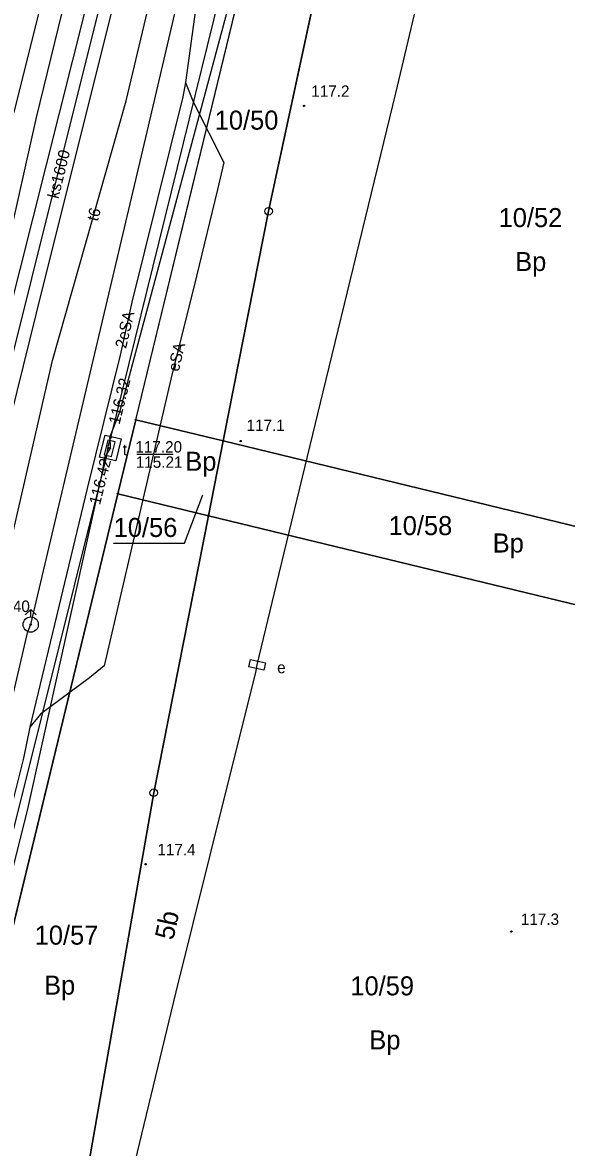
# Model space of a CAD drawing. Extents: x 6424617 to 6425697, y 5665845 to 5667190.
# Drawn here: x 6425314 to 6425349.8, y 5666069.8 to 5666143.7 of the extents above; entities that cross this region are included whole.
import ezdxf

# ---------------------------------------------------------------- set-up
doc = ezdxf.new("R2010")
doc.units = 0
for name, color, linetype in [('Warstwa 1', 7, 'Continuous'), ('Warstwa 10', 7, 'Continuous'), ('Warstwa 11', 7, 'Continuous'), ('Warstwa 12', 7, 'Continuous'), ('Warstwa 13', 7, 'Continuous'), ('Warstwa 14', 7, 'Continuous'), ('Warstwa 15', 7, 'Continuous'), ('Warstwa 16', 7, 'Continuous'), ('Warstwa 2', 7, 'Continuous'), ('Warstwa 21', 7, 'Continuous'), ('Warstwa 4', 7, 'Continuous'), ('Warstwa 5', 7, 'Continuous'), ('Warstwa 6', 7, 'Continuous'), ('Warstwa 61', 7, 'Continuous'), ('Warstwa 9', 7, 'Continuous')]:
    doc.layers.add(name, color=color, linetype=linetype)

msp = doc.modelspace()

# ---------------------------------------------------------------- linework, layer by layer
at = {"layer": 'Warstwa 1'}
for p, q in [((6425321.48, 5666117.61), (6425331.55, 5666159.11)), ((6425321.48, 5666117.61), (6425331.55, 5666159.11)), ((6425330.199, 5666131.309), (6425335.94, 5666158.04)), ((6425330.199, 5666131.309), (6425335.94, 5666158.04)), ((6425327.22, 5666116.22), (6425330.199, 5666131.309)), ((6425327.22, 5666116.22), (6425330.199, 5666131.309)), ((6425320.3, 5666112.75), (6425321.48, 5666117.61)), ((6425320.3, 5666112.75), (6425321.48, 5666117.61)), ((6425321.48, 5666117.61), (6425327.22, 5666116.22)), ((6425321.48, 5666117.61), (6425327.22, 5666116.22)), ((6425326.25, 5666111.31), (6425327.22, 5666116.22)), ((6425326.25, 5666111.31), (6425327.22, 5666116.22)), ((6425327.22, 5666116.22), (6425364.28, 5666107.23)), ((6425327.22, 5666116.22), (6425364.28, 5666107.23)), ((6425307.383, 5666059.502), (6425320.3, 5666112.75)), ((6425307.383, 5666059.502), (6425320.3, 5666112.75)), ((6425320.3, 5666112.75), (6425326.25, 5666111.31)), ((6425320.3, 5666112.75), (6425326.25, 5666111.31)), ((6425322.659, 5666093.11), (6425326.25, 5666111.31)), ((6425322.659, 5666093.11), (6425326.25, 5666111.31)), ((6425326.25, 5666111.31), (6425363.13, 5666102.36)), ((6425326.25, 5666111.31), (6425363.13, 5666102.36)), ((6425314.293, 5666045.457), (6425322.659, 5666093.11)), ((6425314.293, 5666045.457), (6425322.659, 5666093.11))]:
    msp.add_line(p, q, dxfattribs=at)
at = {"layer": 'Warstwa 10'}
for points in [[(6425366.705, 5666313.952), (6425364.98, 5666307.394), (6425362.943, 5666299.196), (6425357.643, 5666277.187), (6425356.335, 5666271.53), (6425352.738, 5666256.719), (6425351.907, 5666252.99), (6425349.316, 5666242.152), (6425345.12, 5666224.971), (6425343.235, 5666216.898), (6425341.343, 5666209.098), (6425332.507, 5666173.528), (6425329.622, 5666162.257), (6425325.627, 5666146.18), (6425324.735, 5666139.771)], [(6425324.735, 5666139.771), (6425325.272, 5666138.452), (6425327.252, 5666134.518), (6425326.853, 5666132.742), (6425325.46, 5666127.052), (6425323.784, 5666120.273), (6425319.4, 5666101.45), (6425318.435, 5666100.665), (6425315.212, 5666098.266), (6425314.516, 5666097.411)], [(6425324.735, 5666139.771), (6425324.567, 5666138.82), (6425321.214, 5666125.338), (6425320.452, 5666121.863), (6425318.28, 5666113.101), (6425314.516, 5666097.411)], [(6425314.516, 5666097.411), (6425314.113, 5666095.387), (6425310.83, 5666082.329), (6425309.435, 5666076.765), (6425308.31, 5666071.803), (6425306.533, 5666064.673)]]:
    msp.add_lwpolyline(points, dxfattribs=at)
for centre in [(6425330.199, 5666131.309), (6425322.659, 5666093.11)]:
    msp.add_circle(centre, 0.25, dxfattribs=at)
at = {"layer": 'Warstwa 12'}
for points in [[(6425305.154, 5666064.69), (6425312.938, 5666097.478), (6425314.389, 5666103.694), (6425314.577, 5666104.157), (6425322.215, 5666136.517), (6425325.077, 5666148.728), (6425327.095, 5666157.317), (6425332.422, 5666179.712), (6425334.472, 5666188.347), (6425337.66, 5666202.127), (6425337.727, 5666202.623), (6425340.397, 5666213.727), (6425347.877, 5666245.554), (6425350.108, 5666255.243), (6425354.52, 5666274.46), (6425358.124, 5666289.983), (6425360.543, 5666300.182), (6425364.084, 5666313.984)], [(6425302.996, 5666064.716), (6425303.371, 5666066.959), (6425303.474, 5666067.683), (6425303.814, 5666068.412), (6425304.651, 5666073.489), (6425307.939, 5666085.989), (6425311.229, 5666100.781), (6425315.998, 5666121.507), (6425320.84, 5666138.568), (6425327.293, 5666165.729), (6425330.741, 5666179.714), (6425331.41, 5666183.678), (6425331.223, 5666184.439), (6425337.86, 5666212.626), (6425344.087, 5666240.981), (6425358.931, 5666300.334), (6425358.838, 5666300.979)], [(6425320.382, 5666064.506), (6425324.122, 5666080.024), (6425327.46, 5666093.416), (6425329.355, 5666100.998), (6425329.449, 5666101.506), (6425330.718, 5666106.78), (6425333.785, 5666119.439), (6425338.549, 5666139.062), (6425341.864, 5666153.037), (6425342.705, 5666156.012), (6425344.677, 5666164.319), (6425345.935, 5666169.368), (6425348.182, 5666178.762), (6425351.749, 5666193.731), (6425354.241, 5666204.098)], [(6425338.063, 5666190.341), (6425337.711, 5666188.983), (6425319.81, 5666116.414), (6425319.643, 5666115.857), (6425319.556, 5666115.245), (6425306.92, 5666064.668)], [(6425307.484, 5666064.661), (6425308.087, 5666066.909), (6425314.371, 5666091.949), (6425319.287, 5666114.171), (6425319.45, 5666115.139), (6425319.807, 5666115.746), (6425319.784, 5666116.517), (6425320.436, 5666118.136), (6425328.2, 5666147.128), (6425329.097, 5666150.261), (6425330.794, 5666156.413), (6425337.552, 5666188.452), (6425337.922, 5666190.227)], [(6425327.353, 5666180.631), (6425325.599, 5666173.711), (6425322.908, 5666163.318), (6425318.178, 5666144.632), (6425313.866, 5666127.482), (6425308.085, 5666104.552), (6425305.278, 5666093.33), (6425304.482, 5666090.216)], [(6425306.182, 5666089.671), (6425311.135, 5666109.171), (6425315.382, 5666126.297), (6425321.264, 5666149.87), (6425326.891, 5666171.984), (6425329.037, 5666180.221)]]:
    msp.add_lwpolyline(points, dxfattribs=at)
for centre in [(6425321.48, 5666117.61), (6425327.22, 5666116.22), (6425320.3, 5666112.75), (6425326.25, 5666111.31)]:
    msp.add_circle(centre, 0.045, dxfattribs=at)
at = {"layer": 'Warstwa 13'}
for centre in [(6425332.534, 5666138.227), (6425328.357, 5666116.207), (6425322.123, 5666088.408), (6425346.141, 5666083.992)]:
    msp.add_circle(centre, 0.045, dxfattribs=at)
at = {"layer": 'Warstwa 14'}
msp.add_line((6425323.929, 5666115.33), (6425321.549, 5666115.33), dxfattribs=at)
for centre in [(6425319.81, 5666116.414), (6425319.768, 5666115.733), (6425319.45, 5666115.139), (6425314.577, 5666104.157)]:
    msp.add_circle(centre, 0.045, dxfattribs=at)
at = {"layer": 'Warstwa 15'}
msp.add_lwpolyline([(6425320.024, 5666109.5), (6425324.669, 5666109.5), (6425325.872, 5666112.681)], dxfattribs=at)
at = {"layer": 'Warstwa 16'}
msp.add_lwpolyline([(6425319.457, 5666116.589), (6425320.507, 5666116.348), (6425320.166, 5666114.902), (6425319.098, 5666115.153)], close=True, dxfattribs=at)
at = {"layer": 'Warstwa 21'}
msp.add_lwpolyline([(6425329.881, 5666101.151), (6425328.906, 5666101.373), (6425329.017, 5666101.861), (6425329.992, 5666101.639), (6425329.881, 5666101.151)], dxfattribs=at)
at = {"layer": 'Warstwa 4'}
msp.add_lwpolyline([(6425319.893, 5666115.188), (6425320.129, 5666116.16), (6425319.643, 5666116.278), (6425319.407, 5666115.306)], close=True, dxfattribs=at)
for points in [[(6425314.223, 5666104.803), (6425314.577, 5666105.157)], [(6425314.931, 5666104.803), (6425314.577, 5666105.157)], [(6425314.577, 5666104.657), (6425314.577, 5666105.157)]]:
    msp.add_lwpolyline(points, dxfattribs=at)
msp.add_circle((6425314.577, 5666104.157), 0.5, dxfattribs=at)
at = {"layer": 'Warstwa 5'}
msp.add_line((6425313.49, 5666137.803), (6425317.654, 5666154.563), dxfattribs=at)
at = {"layer": 'Warstwa 6'}
msp.add_lwpolyline([(6425325.89, 5666241.74), (6425306.64, 5666159.22), (6425302.03, 5666141.46), (6425286.06, 5666058.16), (6425282.55, 5666028.38), (6425277.55, 5665972.9), (6425261.42, 5665964.23), (6425258.752, 5665937.662), (6425276.622, 5665932.707), (6425278.506, 5665940.485), (6425294.186, 5666005.104), (6425300.721, 5666032.019), (6425302.837, 5666040.775), (6425307.383, 5666059.502), (6425320.3, 5666112.75), (6425321.48, 5666117.61), (6425331.55, 5666159.11), (6425352.539, 5666245.598)], dxfattribs=at)
for points in [[(6425335.94, 5666158.04), (6425330.199, 5666131.309), (6425327.22, 5666116.22), (6425321.48, 5666117.61), (6425331.55, 5666159.11)], [(6425335.94, 5666158.04), (6425330.199, 5666131.309), (6425327.22, 5666116.22), (6425364.28, 5666107.23), (6425374.12, 5666148.78)], [(6425321.48, 5666117.61), (6425320.3, 5666112.75), (6425326.25, 5666111.31), (6425327.22, 5666116.22)], [(6425327.22, 5666116.22), (6425326.25, 5666111.31), (6425363.13, 5666102.36), (6425364.28, 5666107.23)], [(6425320.3, 5666112.75), (6425307.383, 5666059.502), (6425314.293, 5666045.457), (6425322.659, 5666093.11), (6425326.25, 5666111.31)], [(6425326.25, 5666111.31), (6425322.659, 5666093.11), (6425314.293, 5666045.457), (6425318.442, 5666037.006), (6425346.072, 5666030.351), (6425363.13, 5666102.36)]]:
    msp.add_lwpolyline(points, close=True, dxfattribs=at)
at = {"layer": 'Warstwa 61'}
msp.add_lwpolyline([(6425339.763, 5666232.165), (6425339.761, 5666232.156), (6425339.742, 5666231.982), (6425339.674, 5666231.816), (6425339.52, 5666231.124), (6425339.474, 5666230.402), (6425328.534, 5666181.84), (6425328.383, 5666181.129), (6425328.195, 5666180.427), (6425326.245, 5666172.848), (6425323.743, 5666163.106), (6425320.437, 5666150.079), (6425319.015, 5666144.423), (6425314.624, 5666126.89), (6425310.249, 5666109.394), (6425308.966, 5666104.328), (6425306.139, 5666093.111), (6425305.332, 5666089.944), (6425305.847, 5666088.59), (6425304.771, 5666087.747), (6425304.116, 5666085.226), (6425303.568, 5666082.998), (6425302.64, 5666079.196)], dxfattribs=at)
at = {"layer": 'Warstwa 9'}
for p, q in [((6425313.49, 5666137.803), (6425317.654, 5666154.563)), ((6425314.954, 5666137.466), (6425319.058, 5666154.218)), ((6425313.017, 5666128.758), (6425314.954, 5666137.466))]:
    msp.add_line(p, q, dxfattribs=at)

# ---------------------------------------------------------------- texts
at = {"layer": 'Warstwa 11'}
for s, rotation, p in [('2eSA', 76.91958, (6425320.837, 5666122.252)), ('eSA', 76.80499, (6425324.295, 5666120.734))]:
    msp.add_text(s, height=0.75, rotation=rotation, dxfattribs=at).set_placement(p)
at = {"layer": 'Warstwa 13'}
for s, p in [('117.2', (6425333.003, 5666138.824)), ('117.1', (6425328.751, 5666116.869)), ('117.4', (6425322.896, 5666089.001)), ('117.3', (6425346.767, 5666084.426))]:
    msp.add_text(s, height=0.75, dxfattribs=at).set_placement(p)
for s, rotation, p in [('ks1600', 75.99139, (6425316.393, 5666132.091)), ('t6', 74.15793, (6425318.969, 5666130.603))]:
    msp.add_text(s, height=0.75, rotation=rotation, dxfattribs=at).set_placement(p)
at = {"layer": 'Warstwa 14'}
for s, height, rotation, p in [('116.32', 0.75, 76.14036, (6425320.405, 5666117.261)), ('116.42', 0.75, 75.9742, (6425319.126, 5666111.979)), ('5b', 1.25, 77.73318, (6425323.94, 5666083.38))]:
    msp.add_text(s, height=height, rotation=rotation, dxfattribs=at).set_placement(p)
msp.add_text('115.21', height=0.75, dxfattribs=at).set_placement((6425321.476, 5666114.455))
at = {"layer": 'Warstwa 15'}
for s, height, p in [('10/50', 1.25, (6425326.661, 5666136.669)), ('10/52', 1.25, (6425345.305, 5666130.266)), ('117.20', 0.75, (6425321.449, 5666115.455)), ('10/56', 1.25, (6425320.024, 5666109.912)), ('10/58', 1.25, (6425338.079, 5666110.033)), ('117.40', 0.75, (6425311.453, 5666104.983)), ('10/57', 1.25, (6425314.837, 5666083.131)), ('10/59', 1.25, (6425335.57, 5666079.799))]:
    msp.add_text(s, height=height, dxfattribs=at).set_placement(p)
at = {"layer": 'Warstwa 2'}
for p in [(6425346.393, 5666127.382), (6425324.728, 5666114.259), (6425344.92, 5666108.891), (6425315.456, 5666079.846), (6425336.816, 5666076.251)]:
    msp.add_text('Bp', height=1.25, dxfattribs=at).set_placement(p)
at = {"layer": 'Warstwa 21'}
msp.add_text('e', height=0.75, dxfattribs=at).set_placement((6425330.761, 5666100.964))
at = {"layer": 'Warstwa 5'}
msp.add_text('t', height=0.75, dxfattribs=at).set_placement((6425320.622, 5666115.279))

doc.saveas('drawing.dxf')
